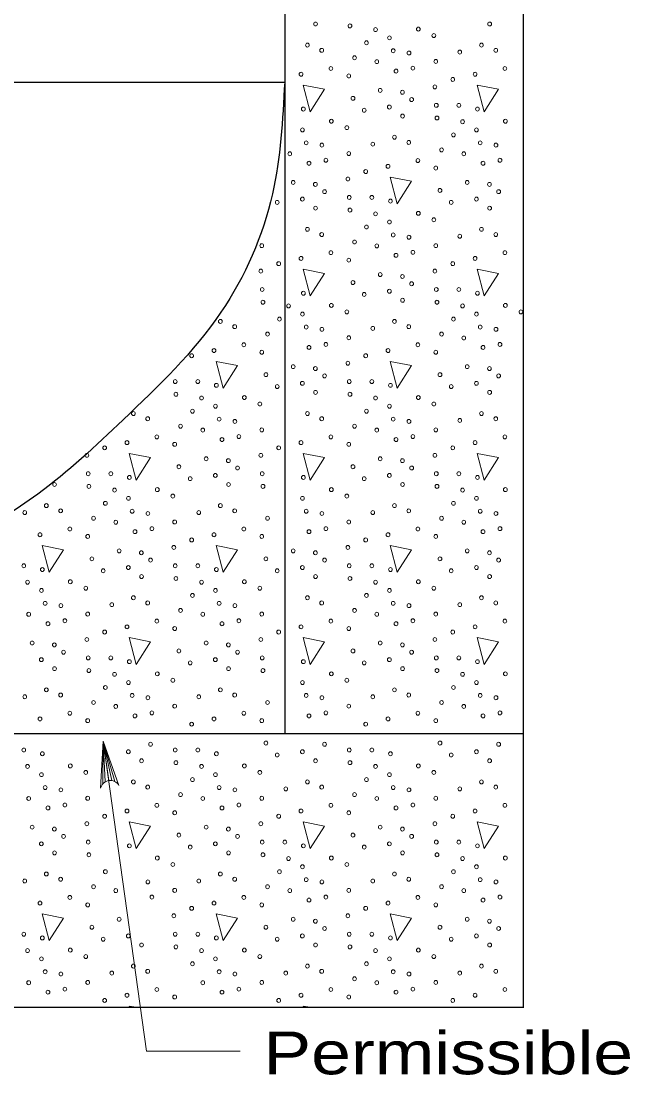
# Model space of a CAD drawing. Extents: x 1083.1 to 1117.1, y 697.4 to 719.4.
# Drawn here: x 1097.699 to 1099.918, y 700.074 to 703.916 of the extents above; entities that cross this region are included whole.
import ezdxf

# ---------------------------------------------------------------- set-up
doc = ezdxf.new("R2010")
doc.units = 0
doc.header["$LTSCALE"] = 0.062
doc.layers.add('1', color=7, linetype='Continuous', lineweight=13)

msp = doc.modelspace()

# ---------------------------------------------------------------- linework, layer by layer
at = {"layer": '1', "lineweight": 25}
for p, q in [((1098.65942, 710.471), (1098.65942, 703.65408)), ((1099.52967, 700.32125), (1099.52967, 710.48467)), ((1094.39417, 703.69325), (1098.65942, 703.69325)), ((1098.65942, 703.65408), (1098.65942, 701.31858)), ((1094.39242, 701.31858), (1099.53092, 701.31858))]:
    msp.add_line(p, q, dxfattribs=at)
at = {"layer": '1'}
for p, q in [((1097.9965, 701.13483), (1097.99783, 701.29067)), ((1098.01858, 701.14658), (1097.99783, 701.29067)), ((1098.00542, 701.142), (1097.99783, 701.29067)), ((1098.0295, 701.14658), (1097.99783, 701.29067)), ((1098.04067, 701.143), (1097.99783, 701.29067)), ((1098.09233, 700.32467), (1098.09325, 700.32133)), ((1098.10983, 700.32133), (1098.09233, 700.32467)), ((1098.72675, 700.32467), (1098.72775, 700.32133)), ((1098.74433, 700.32133), (1098.72675, 700.32467))]:
    msp.add_line(p, q, dxfattribs=at)
for points in [[(1098.72675, 703.68292), (1098.75242, 703.58558), (1098.80458, 703.66775)], [(1099.36117, 703.68292), (1099.38675, 703.58558), (1099.439, 703.66775)], [(1099.04392, 703.34708), (1099.06958, 703.24975), (1099.12183, 703.33192)], [(1098.72675, 703.01125), (1098.75242, 702.91392), (1098.80458, 702.99608)], [(1099.36117, 703.01125), (1099.38675, 702.91392), (1099.439, 702.99608)], [(1098.4095, 702.67542), (1098.43517, 702.57808), (1098.48742, 702.66025)], [(1099.04392, 702.67542), (1099.06958, 702.57808), (1099.12183, 702.66025)], [(1098.09233, 702.33958), (1098.11792, 702.24225), (1098.17017, 702.32442)], [(1098.72675, 702.33958), (1098.75242, 702.24225), (1098.80458, 702.32442)], [(1099.36117, 702.33958), (1099.38675, 702.24225), (1099.439, 702.32442)], [(1097.77517, 702.00375), (1097.80075, 701.9065), (1097.853, 701.98867)], [(1098.4095, 702.00375), (1098.43517, 701.9065), (1098.48742, 701.98867)], [(1099.04392, 702.00375), (1099.06958, 701.9065), (1099.12183, 701.98867)], [(1098.09233, 701.668), (1098.11792, 701.57058), (1098.17017, 701.65275)], [(1098.72675, 701.668), (1098.75242, 701.57058), (1098.80458, 701.65275)], [(1099.36117, 701.668), (1099.38675, 701.57058), (1099.439, 701.65275)], [(1098.09233, 700.99625), (1098.11792, 700.899), (1098.17017, 700.98117)], [(1098.72675, 700.99625), (1098.75242, 700.899), (1098.80458, 700.98117)], [(1099.36117, 700.99625), (1099.38675, 700.899), (1099.439, 700.98117)], [(1097.77517, 700.6605), (1097.80075, 700.56317), (1097.853, 700.64533)], [(1098.4095, 700.6605), (1098.43517, 700.56317), (1098.48742, 700.64533)], [(1099.04392, 700.6605), (1099.06958, 700.56317), (1099.12183, 700.64533)]]:
    msp.add_lwpolyline(points, close=True, dxfattribs=at)
for points in [[(1097.9885, 701.11942), (1097.99783, 701.29067), (1098.05508, 701.129)], [(1097.99783, 701.29067), (1098.15633, 700.16042), (1098.49658, 700.16042)]]:
    msp.add_lwpolyline(points, dxfattribs=at)
at = {"layer": '1', "lineweight": 25}
msp.add_lwpolyline([(1093.91333, 700.98025), (1093.91333, 700.32125), (1099.53092, 700.32125)], dxfattribs=at)
at = {"layer": '1'}
msp.add_arc((1098.02379, 701.11074), 0.03631, 30.29065, 166.11677, dxfattribs=at)
for centre in [(1098.77219, 703.90561), (1098.89749, 703.89867), (1098.9909, 703.88507), (1099.14675, 703.88686), (1099.40659, 703.90561), (1099.04139, 703.85513), (1099.20327, 703.8633), (1098.74222, 703.82854), (1098.79445, 703.80951), (1098.95744, 703.83699), (1099.05514, 703.808), (1099.1125, 703.79977), (1099.29779, 703.80319), (1099.37662, 703.82854), (1099.42885, 703.80951), (1098.91435, 703.78231), (1098.99513, 703.76809), (1099.21014, 703.76893), (1098.71906, 703.72242), (1098.82781, 703.7433), (1099.06534, 703.73362), (1099.12703, 703.74453), (1099.35346, 703.72242), (1099.46221, 703.7433), (1098.89294, 703.7161), (1099.27205, 703.70339), (1099.00771, 703.66354), (1099.08855, 703.65654), (1099.20702, 703.67619), (1098.90838, 703.63449), (1099.12222, 703.62996), (1099.21215, 703.60908), (1099.29441, 703.60908), (1098.72763, 703.59548), (1098.94951, 703.59095), (1099.04113, 703.60276), (1099.08939, 703.56979), (1099.36203, 703.59548), (1098.82955, 703.55104), (1099.21469, 703.56285), (1099.3081, 703.54925), (1099.46395, 703.55104), (1098.72419, 703.5193), (1098.88607, 703.52748), (1099.05942, 703.49272), (1099.27464, 703.50117), (1099.35859, 703.5193), (1098.73793, 703.47218), (1098.79529, 703.46395), (1098.98059, 703.46736), (1099.11165, 703.47369), (1099.37234, 703.47218), (1099.4297, 703.46395), (1098.67793, 703.43227), (1098.89294, 703.43311), (1099.23155, 703.44649), (1099.31233, 703.43227), (1098.74814, 703.39779), (1098.80983, 703.40871), (1099.03626, 703.3866), (1099.14501, 703.40747), (1099.21014, 703.38027), (1099.38254, 703.39779), (1099.44424, 703.40871), (1098.88982, 703.34037), (1098.95485, 703.36757), (1098.69051, 703.32772), (1098.77135, 703.32072), (1099.32491, 703.32772), (1099.40575, 703.32072), (1098.72392, 703.26693), (1098.80502, 703.29413), (1098.89495, 703.27326), (1098.97721, 703.27326), (1099.22558, 703.29867), (1099.35833, 703.26693), (1099.43942, 703.29413), (1098.63231, 703.25512), (1098.77219, 703.23396), (1098.89749, 703.22702), (1099.04483, 703.25966), (1099.26671, 703.25512), (1099.40659, 703.23396), (1098.9909, 703.21342), (1099.14675, 703.21521), (1099.20327, 703.19165), (1098.74222, 703.15689), (1098.95744, 703.16534), (1099.04139, 703.18348), (1099.37662, 703.15689), (1098.79445, 703.13786), (1098.91435, 703.11066), (1099.05514, 703.13635), (1099.1125, 703.12812), (1099.29779, 703.13154), (1099.42885, 703.13786), (1098.57574, 703.09728), (1098.82781, 703.07165), (1098.99513, 703.09644), (1099.12703, 703.07288), (1099.21014, 703.09728), (1099.46221, 703.07165), (1098.63765, 703.03174), (1098.71906, 703.05077), (1098.89294, 703.04445), (1099.06534, 703.06197), (1099.27205, 703.03174), (1099.35346, 703.05077), (1098.57262, 703.00454), (1099.00771, 702.99189), (1099.20702, 703.00454), (1098.90838, 702.96284), (1099.08855, 702.98489), (1099.12222, 702.95831), (1098.57775, 702.93743), (1098.72763, 702.92383), (1098.94951, 702.9193), (1099.04113, 702.93111), (1099.21215, 702.93743), (1099.29441, 702.93743), (1099.36203, 702.92383), (1098.58029, 702.8912), (1098.6737, 702.8776), (1098.82955, 702.87939), (1099.08939, 702.89814), (1099.21469, 702.8912), (1099.3081, 702.8776), (1099.46395, 702.87939), (1098.72419, 702.84765), (1098.88607, 702.85583), (1099.35859, 702.84765), (1099.52047, 702.85583), (1098.42502, 702.82107), (1098.47725, 702.80204), (1098.64024, 702.82952), (1098.73793, 702.80053), (1099.05942, 702.82107), (1099.11165, 702.80204), (1099.27464, 702.82952), (1099.37234, 702.80053), (1098.59715, 702.77484), (1098.79529, 702.7923), (1098.89294, 702.76146), (1098.98059, 702.79571), (1099.23155, 702.77484), (1099.4297, 702.7923), (1098.51061, 702.73583), (1098.74814, 702.72614), (1098.80983, 702.73706), (1099.14501, 702.73583), (1099.31233, 702.76062), (1099.38254, 702.72614), (1099.44424, 702.73706), (1098.32044, 702.69592), (1098.40186, 702.71495), (1098.57574, 702.70862), (1098.95485, 702.69592), (1099.03626, 702.71495), (1099.21014, 702.70862), (1098.69051, 702.65607), (1098.77135, 702.64907), (1098.88982, 702.66872), (1099.32491, 702.65607), (1099.40575, 702.64907), (1098.59118, 702.62702), (1098.80502, 702.62248), (1099.22558, 702.62702), (1099.43942, 702.62248), (1098.26055, 702.60161), (1098.34281, 702.60161), (1098.41042, 702.58801), (1098.63231, 702.58347), (1098.72392, 702.59528), (1098.89495, 702.60161), (1098.97721, 702.60161), (1099.04483, 702.58801), (1099.26671, 702.58347), (1099.35833, 702.59528), (1098.26308, 702.55538), (1098.3565, 702.54177), (1098.51235, 702.54357), (1098.77219, 702.56232), (1098.89749, 702.55538), (1098.9909, 702.54177), (1099.14675, 702.54357), (1099.40659, 702.56232), (1098.32304, 702.4937), (1098.40699, 702.51183), (1098.56887, 702.52), (1098.95744, 702.4937), (1099.04139, 702.51183), (1099.20327, 702.52), (1098.10781, 702.48524), (1098.16005, 702.46621), (1098.42073, 702.4647), (1098.47809, 702.45648), (1098.74222, 702.48524), (1098.79445, 702.46621), (1099.05514, 702.4647), (1099.1125, 702.45648), (1099.29779, 702.45989), (1099.37662, 702.48524), (1099.42885, 702.46621), (1098.27995, 702.43901), (1098.36073, 702.4248), (1098.57574, 702.42564), (1098.91435, 702.43901), (1098.99513, 702.4248), (1099.21014, 702.42564), (1098.08466, 702.37912), (1098.19341, 702.4), (1098.43094, 702.39032), (1098.49263, 702.40123), (1098.71906, 702.37912), (1098.82781, 702.4), (1099.06534, 702.39032), (1099.12703, 702.40123), (1099.35346, 702.37912), (1099.46221, 702.4), (1098.00324, 702.36009), (1098.25854, 702.3728), (1098.63765, 702.36009), (1098.89294, 702.3728), (1099.27205, 702.36009), (1097.93822, 702.33289), (1098.37331, 702.32024), (1098.45415, 702.31325), (1098.57262, 702.33289), (1099.00771, 702.32024), (1099.08855, 702.31325), (1099.20702, 702.33289), (1097.94335, 702.26578), (1098.02561, 702.26578), (1098.27398, 702.29119), (1098.48782, 702.28666), (1098.57775, 702.26578), (1098.90838, 702.29119), (1099.12222, 702.28666), (1099.21215, 702.26578), (1099.29441, 702.26578), (1097.82059, 702.22649), (1098.09322, 702.25218), (1098.31511, 702.24765), (1098.40672, 702.25946), (1098.45499, 702.22649), (1098.72763, 702.25218), (1098.94951, 702.24765), (1099.04113, 702.25946), (1099.08939, 702.22649), (1099.36203, 702.25218), (1097.94588, 702.21955), (1098.0393, 702.20595), (1098.19515, 702.20774), (1098.58029, 702.21955), (1098.82955, 702.20774), (1099.21469, 702.21955), (1099.3081, 702.20595), (1099.46395, 702.20774), (1097.79061, 702.14942), (1098.00583, 702.15787), (1098.08979, 702.17601), (1098.25167, 702.18418), (1098.42502, 702.14942), (1098.72419, 702.17601), (1098.88607, 702.18418), (1099.05942, 702.14942), (1099.27464, 702.15787), (1099.35859, 702.17601), (1097.71179, 702.12406), (1097.84285, 702.13039), (1098.10353, 702.12888), (1098.16089, 702.12065), (1098.34619, 702.12406), (1098.47725, 702.13039), (1098.73793, 702.12888), (1098.79529, 702.12065), (1098.98059, 702.12406), (1099.11165, 702.13039), (1099.37234, 702.12888), (1099.4297, 702.12065), (1097.96275, 702.10319), (1098.04353, 702.08897), (1098.25854, 702.08981), (1098.59715, 702.10319), (1098.89294, 702.08981), (1099.23155, 702.10319), (1099.31233, 702.08897), (1097.76746, 702.0433), (1097.8762, 702.06418), (1097.94134, 702.03697), (1098.11374, 702.05449), (1098.17543, 702.06541), (1098.40186, 702.0433), (1098.51061, 702.06418), (1098.57574, 702.03697), (1098.74814, 702.05449), (1098.80983, 702.06541), (1099.03626, 702.0433), (1099.14501, 702.06418), (1099.21014, 702.03697), (1099.38254, 702.05449), (1099.44424, 702.06541), (1098.25542, 701.99707), (1098.32044, 702.02427), (1098.88982, 701.99707), (1098.95485, 702.02427), (1097.95677, 701.95537), (1098.05611, 701.98442), (1098.13694, 701.97742), (1098.59118, 701.95537), (1098.69051, 701.98442), (1098.77135, 701.97742), (1099.22558, 701.95537), (1099.32491, 701.98442), (1099.40575, 701.97742), (1097.70841, 701.92996), (1097.77602, 701.91636), (1098.08952, 701.92363), (1098.17062, 701.95084), (1098.26055, 701.92996), (1098.34281, 701.92996), (1098.41042, 701.91636), (1098.72392, 701.92363), (1098.80502, 701.95084), (1098.89495, 701.92996), (1098.97721, 701.92996), (1099.04483, 701.91636), (1099.35833, 701.92363), (1099.43942, 701.95084), (1097.9979, 701.91182), (1098.13779, 701.89067), (1098.26308, 701.88373), (1098.63231, 701.91182), (1098.77219, 701.89067), (1098.89749, 701.88373), (1099.26671, 701.91182), (1099.40659, 701.89067), (1097.7221, 701.87013), (1097.77259, 701.84018), (1097.87795, 701.87192), (1097.93446, 701.84835), (1098.3565, 701.87013), (1098.40699, 701.84018), (1098.51235, 701.87192), (1098.56887, 701.84835), (1098.9909, 701.87013), (1099.04139, 701.84018), (1099.14675, 701.87192), (1099.20327, 701.84835), (1098.10781, 701.81359), (1098.32304, 701.82205), (1098.74222, 701.81359), (1098.95744, 701.82205), (1099.37662, 701.81359), (1097.78633, 701.79305), (1097.84369, 701.78483), (1098.02899, 701.78824), (1098.16005, 701.79456), (1098.27995, 701.76736), (1098.42073, 701.79305), (1098.47809, 701.78483), (1098.79445, 701.79456), (1098.91435, 701.76736), (1099.05514, 701.79305), (1099.1125, 701.78483), (1099.29779, 701.78824), (1099.42885, 701.79456), (1097.72633, 701.75315), (1097.85823, 701.72958), (1097.94134, 701.75399), (1098.19341, 701.72835), (1098.36073, 701.75315), (1098.49263, 701.72958), (1098.57574, 701.75399), (1098.82781, 701.72835), (1098.99513, 701.75315), (1099.12703, 701.72958), (1099.21014, 701.75399), (1099.46221, 701.72835), (1097.79653, 701.71867), (1098.00324, 701.68844), (1098.08466, 701.70747), (1098.25854, 701.70115), (1098.43094, 701.71867), (1098.63765, 701.68844), (1098.71906, 701.70747), (1098.89294, 701.70115), (1099.06534, 701.71867), (1099.27205, 701.68844), (1099.35346, 701.70747), (1097.73891, 701.64859), (1097.93822, 701.66124), (1098.37331, 701.64859), (1098.57262, 701.66124), (1099.00771, 701.64859), (1099.20702, 701.66124), (1097.81974, 701.6416), (1097.85342, 701.61501), (1098.27398, 701.61954), (1098.45415, 701.6416), (1098.48782, 701.61501), (1098.90838, 701.61954), (1099.08855, 701.6416), (1099.12222, 701.61501), (1097.77232, 701.58781), (1097.94335, 701.59413), (1098.02561, 701.59413), (1098.09322, 701.58053), (1098.31511, 701.576), (1098.40672, 701.58781), (1098.57775, 701.59413), (1098.72763, 701.58053), (1098.94951, 701.576), (1099.04113, 701.58781), (1099.21215, 701.59413), (1099.29441, 701.59413), (1099.36203, 701.58053), (1097.82059, 701.55484), (1097.94588, 701.5479), (1098.0393, 701.5343), (1098.19515, 701.53609), (1098.45499, 701.55484), (1098.58029, 701.5479), (1098.82955, 701.53609), (1099.08939, 701.55484), (1099.21469, 701.5479), (1099.3081, 701.5343), (1099.46395, 701.53609), (1098.08979, 701.50436), (1098.25167, 701.51253), (1098.72419, 701.50436), (1098.88607, 701.51253), (1099.35859, 701.50436), (1097.79061, 701.47777), (1097.84285, 701.45874), (1098.00583, 701.48622), (1098.10353, 701.45723), (1098.42502, 701.47777), (1098.47725, 701.45874), (1098.73793, 701.45723), (1099.05942, 701.47777), (1099.11165, 701.45874), (1099.27464, 701.48622), (1099.37234, 701.45723), (1097.71179, 701.45242), (1097.96275, 701.43154), (1098.04353, 701.41732), (1098.16089, 701.449), (1098.25854, 701.41816), (1098.34619, 701.45242), (1098.59715, 701.43154), (1098.79529, 701.449), (1098.89294, 701.41816), (1098.98059, 701.45242), (1099.23155, 701.43154), (1099.31233, 701.41732), (1099.4297, 701.449), (1097.8762, 701.39253), (1098.11374, 701.38284), (1098.17543, 701.39376), (1098.51061, 701.39253), (1098.74814, 701.38284), (1098.80983, 701.39376), (1099.14501, 701.39253), (1099.38254, 701.38284), (1099.44424, 701.39376), (1097.76746, 701.37165), (1097.94134, 701.36533), (1098.32044, 701.35262), (1098.40186, 701.37165), (1098.57574, 701.36533), (1098.95485, 701.35262), (1099.03626, 701.37165), (1099.21014, 701.36533), (1098.17062, 701.27919), (1098.59118, 701.28372), (1098.80502, 701.27919), (1099.22558, 701.28372), (1099.43942, 701.27919), (1097.70841, 701.25831), (1097.77602, 701.24471), (1098.08952, 701.25198), (1098.26055, 701.25831), (1098.34281, 701.25831), (1098.41042, 701.24471), (1098.63231, 701.24017), (1098.72392, 701.25198), (1098.89495, 701.25831), (1098.97721, 701.25831), (1099.04483, 701.24471), (1099.26671, 701.24017), (1099.35833, 701.25198), (1097.7221, 701.19848), (1097.87795, 701.20027), (1098.13779, 701.21902), (1098.26308, 701.21208), (1098.3565, 701.19848), (1098.51235, 701.20027), (1098.77219, 701.21902), (1098.89749, 701.21208), (1098.9909, 701.19848), (1099.14675, 701.20027), (1099.40659, 701.21902), (1097.77259, 701.16853), (1097.93446, 701.1767), (1098.32304, 701.1504), (1098.40699, 701.16853), (1098.56887, 701.1767), (1098.95744, 701.1504), (1099.04139, 701.16853), (1099.20327, 701.1767), (1097.78633, 701.1214), (1097.84369, 701.11318), (1098.10781, 701.14195), (1098.16005, 701.12292), (1098.42073, 701.1214), (1098.47809, 701.11318), (1098.66339, 701.11659), (1098.74222, 701.14195), (1098.79445, 701.12292), (1099.05514, 701.1214), (1099.1125, 701.11318), (1099.29779, 701.11659), (1099.37662, 701.14195), (1099.42885, 701.12292), (1097.72633, 701.0815), (1097.94134, 701.08234), (1098.27995, 701.09571), (1098.36073, 701.0815), (1098.57574, 701.08234), (1098.91435, 701.09571), (1098.99513, 701.0815), (1099.21014, 701.08234), (1097.79653, 701.04702), (1097.85823, 701.05793), (1098.08466, 701.03583), (1098.19341, 701.0567), (1098.43094, 701.04702), (1098.49263, 701.05793), (1098.71906, 701.03583), (1098.82781, 701.0567), (1099.06534, 701.04702), (1099.12703, 701.05793), (1099.35346, 701.03583), (1099.46221, 701.0567), (1098.00324, 701.0168), (1098.25854, 701.0295), (1098.63765, 701.0168), (1098.89294, 701.0295), (1099.27205, 701.0168), (1097.73891, 700.97694), (1097.81974, 700.96995), (1097.93822, 700.98959), (1098.37331, 700.97694), (1098.45415, 700.96995), (1098.57262, 700.98959), (1099.00771, 700.97694), (1099.08855, 700.96995), (1099.20702, 700.98959), (1097.85342, 700.94336), (1097.94335, 700.92248), (1098.27398, 700.9479), (1098.48782, 700.94336), (1098.57775, 700.92248), (1098.66001, 700.92248), (1098.90838, 700.9479), (1099.12222, 700.94336), (1099.21215, 700.92248), (1099.29441, 700.92248), (1097.77232, 700.91616), (1097.82059, 700.88319), (1098.09322, 700.90888), (1098.31511, 700.90435), (1098.40672, 700.91616), (1098.45499, 700.88319), (1098.72763, 700.90888), (1098.94951, 700.90435), (1099.04113, 700.91616), (1099.08939, 700.88319), (1099.36203, 700.90888), (1097.94588, 700.87625), (1098.19515, 700.86444), (1098.25167, 700.84088), (1098.58029, 700.87625), (1098.6737, 700.86265), (1098.82955, 700.86444), (1098.88607, 700.84088), (1099.21469, 700.87625), (1099.3081, 700.86265), (1099.46395, 700.86444), (1097.79061, 700.80612), (1098.00583, 700.81457), (1098.42502, 700.80612), (1098.64024, 700.81457), (1098.72419, 700.83271), (1099.05942, 700.80612), (1099.27464, 700.81457), (1099.35859, 700.83271), (1097.71179, 700.78077), (1097.84285, 700.78709), (1098.16089, 700.77735), (1098.34619, 700.78077), (1098.47725, 700.78709), (1098.73793, 700.78558), (1098.79529, 700.77735), (1098.98059, 700.78077), (1099.11165, 700.78709), (1099.37234, 700.78558), (1099.4297, 700.77735), (1097.96275, 700.75989), (1098.04353, 700.74567), (1098.25854, 700.74651), (1098.59715, 700.75989), (1098.67793, 700.74567), (1098.89294, 700.74651), (1099.23155, 700.75989), (1099.31233, 700.74567), (1097.76746, 700.7), (1097.8762, 700.72088), (1097.94134, 700.69368), (1098.17543, 700.72211), (1098.40186, 700.7), (1098.51061, 700.72088), (1098.57574, 700.69368), (1098.74814, 700.71119), (1098.80983, 700.72211), (1099.03626, 700.7), (1099.14501, 700.72088), (1099.21014, 700.69368), (1099.38254, 700.71119), (1099.44424, 700.72211), (1098.25542, 700.65377), (1098.32044, 700.68097), (1098.88982, 700.65377), (1098.95485, 700.68097), (1097.95677, 700.61207), (1098.05611, 700.64112), (1098.59118, 700.61207), (1098.69051, 700.64112), (1098.77135, 700.63412), (1099.22558, 700.61207), (1099.32491, 700.64112), (1099.40575, 700.63412), (1097.70841, 700.58666), (1097.77602, 700.57306), (1098.08952, 700.58034), (1098.26055, 700.58666), (1098.34281, 700.58666), (1098.41042, 700.57306), (1098.72392, 700.58034), (1098.80502, 700.60754), (1098.89495, 700.58666), (1098.97721, 700.58666), (1099.04483, 700.57306), (1099.35833, 700.58034), (1099.43942, 700.60754), (1097.9979, 700.56853), (1098.13779, 700.54737), (1098.26308, 700.54043), (1098.63231, 700.56853), (1098.77219, 700.54737), (1098.89749, 700.54043), (1099.26671, 700.56853), (1099.40659, 700.54737), (1097.7221, 700.52683), (1097.77259, 700.49688), (1097.87795, 700.52862), (1097.93446, 700.50505), (1098.3565, 700.52683), (1098.40699, 700.49688), (1098.51235, 700.52862), (1098.56887, 700.50505), (1098.9909, 700.52683), (1099.04139, 700.49688), (1099.14675, 700.52862), (1099.20327, 700.50505), (1098.10781, 700.4703), (1098.32304, 700.47875), (1098.74222, 700.4703), (1098.95744, 700.47875), (1099.37662, 700.4703), (1097.78633, 700.44976), (1097.84369, 700.44153), (1098.02899, 700.44494), (1098.16005, 700.45127), (1098.42073, 700.44976), (1098.47809, 700.44153), (1098.66339, 700.44494), (1098.79445, 700.45127), (1098.91435, 700.42406), (1099.05514, 700.44976), (1099.1125, 700.44153), (1099.29779, 700.44494), (1099.42885, 700.45127), (1097.72633, 700.40985), (1097.85823, 700.38628), (1097.94134, 700.41069), (1098.19341, 700.38505), (1098.36073, 700.40985), (1098.49263, 700.38628), (1098.57574, 700.41069), (1098.82781, 700.38505), (1098.99513, 700.40985), (1099.12703, 700.38628), (1099.21014, 700.41069), (1099.46221, 700.38505), (1097.79653, 700.37537), (1098.00324, 700.34515), (1098.08466, 700.36418), (1098.25854, 700.35785), (1098.43094, 700.37537), (1098.63765, 700.34515), (1098.71906, 700.36418), (1098.89294, 700.35785), (1099.06534, 700.37537), (1099.27205, 700.34515), (1099.35346, 700.36418)]:
    msp.add_ellipse(centre, major_axis=(0, 0.00718), ratio=0.944544, dxfattribs=at)
at = {"layer": '1', "lineweight": 25}
msp.add_spline([(1098.65942, 703.69325), (1098.61475, 703.28575), (1098.42725, 702.85475), (1098.07042, 702.46242), (1097.75942, 702.19125), (1097.49867, 702.02658), (1097.21508, 701.87658), (1097.01842, 701.78933), (1096.61592, 701.62958), (1096.06242, 701.47458), (1095.51817, 701.37292), (1095.17508, 701.34383), (1094.39242, 701.31858)], degree=3, dxfattribs=at)

# ---------------------------------------------------------------- texts
at = {"layer": '1', "width": 1.25}
msp.add_text('Permissible', height=0.156, dxfattribs=at).set_placement((1098.582, 700.07583))

doc.saveas('drawing.dxf')
